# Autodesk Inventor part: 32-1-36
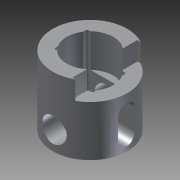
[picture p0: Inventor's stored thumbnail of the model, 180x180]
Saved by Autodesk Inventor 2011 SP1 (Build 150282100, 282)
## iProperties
Created: 2014-02
Part Number: 32-1-36
Document SubType Name: Modeling
Designer: Administrator
Density: 1 g/cm^3
Author: Administrator
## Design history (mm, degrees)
sketch "草图1"
  geometry: C1 r 20 at (0, 0); 1 further point
  constraints: 1 centre point, 1 coincident
  dimensions: "d0" = 40 diameter of C1
extrude "拉伸1" new body sketch "草图1" distance "d1" = 37; taper "d2" = 0 deg
sketch "草图2"
  geometry: L1 (-10.5, -9)-(10.5, -9); L2 (10.5, -9)-(10.5, 9); L3 (10.5, 9)-(-10.5, 9); L4 (-10.5, 9)-(-10.5, -9); C1 r 20 at (0, 0) reference; 2 further points
  constraints: 8 end point, 2 midpoint, 2 parallel, 1 horizontal, 1 horizontal alignment, 1 perpendicular, 1 vertical alignment
  dimensions: "d3" = 21 distance of L1.start L1.end; "d4" = 18 distance of L1.end L2.end
extrude "拉伸2" cut sketch "草图2" stored distance "d5" = 18; taper "d6" = 0 deg
hole "Hole1" diameter "d9" = 25; stored, may be unused: countersink angle "d13" = 90 deg, drill point angle "d15" = 0 deg; dims "d7" = 10, "d8" = 10, "d10" = 6, "d11" = 4, "d12" = 2, "d14" = 18
node "工作平面1"
sketch "草图3"
  geometry: L1 (-20, 0)-(20, 0) reference; C1 r 6.5 at (0, 10); 2 further points
  constraints: 1 centre point, 1 coincident
  dimensions: "d17" = 13 diameter of C1; "d18" = 10 distance of C1.centre point (0, 0)
extrude "拉伸3" cut sketch "草图3" stored distance "d19" = 18; taper "d20" = 0 deg
node "工作平面2"
sketch "草图4"
  geometry: L1 (-20, 0)-(20, 0) reference; L2 (-4.5, 7)-(-4.5, 12.5); L3 (4.5, 7)-(4.5, 12.5); L4 (-4.5, 18)-(-4.5, 12.5); L5 (4.5, 18)-(4.5, 12.5); A1 r 4.5 centre (0, 7) between (-4.5, 7) and (4.5, 7); A2 r 4.5 centre (0, 18) between (4.5, 18) and (-4.5, 18); 1 further point
  constraints: 8 end point, 4 point on circle, 2 centre point, 2 tangent, 1 parallel, 1 perpendicular
  dimensions: "d22" = 9 diameter of A1; "d23" = 7 distance of point (0, 0) A1.centre; "d24" = 5.5 distance of L2.start L2.end
extrude "拉伸4" cut sketch "草图4" stored distance "d25" = 18; taper "d26" = 0 deg
sketch "草图5"
  geometry: L1 (8, -17.5)-(20, -17.5); L2 (20, -17.5)-(20, 17.5); L3 (20, 17.5)-(8, 17.5); L4 (8, 17.5)-(8, -17.5); A1 r 12.5 centre (0, 0) between (-10.5, 6.782) and (-10.5, -6.782) reference; A2 r 12.5 centre (0, 0) between (8.675, 9) and (-8.675, 9) reference; 1 further point
  constraints: 8 end point, 2 parallel, 1 horizontal, 1 horizontal alignment, 1 midpoint, 1 perpendicular
  dimensions: "d27" = 8 distance from line of A2.centre L4; "d30" = 35 distance of L1.end L2.end; "d31" = 12 distance of L2.end L3.end
extrude "拉伸5" cut sketch "草图5" distance "d28" = 10; taper "d29" = 0 deg
fillet "圆角1" dims "d32" = 1
node "实体1"
